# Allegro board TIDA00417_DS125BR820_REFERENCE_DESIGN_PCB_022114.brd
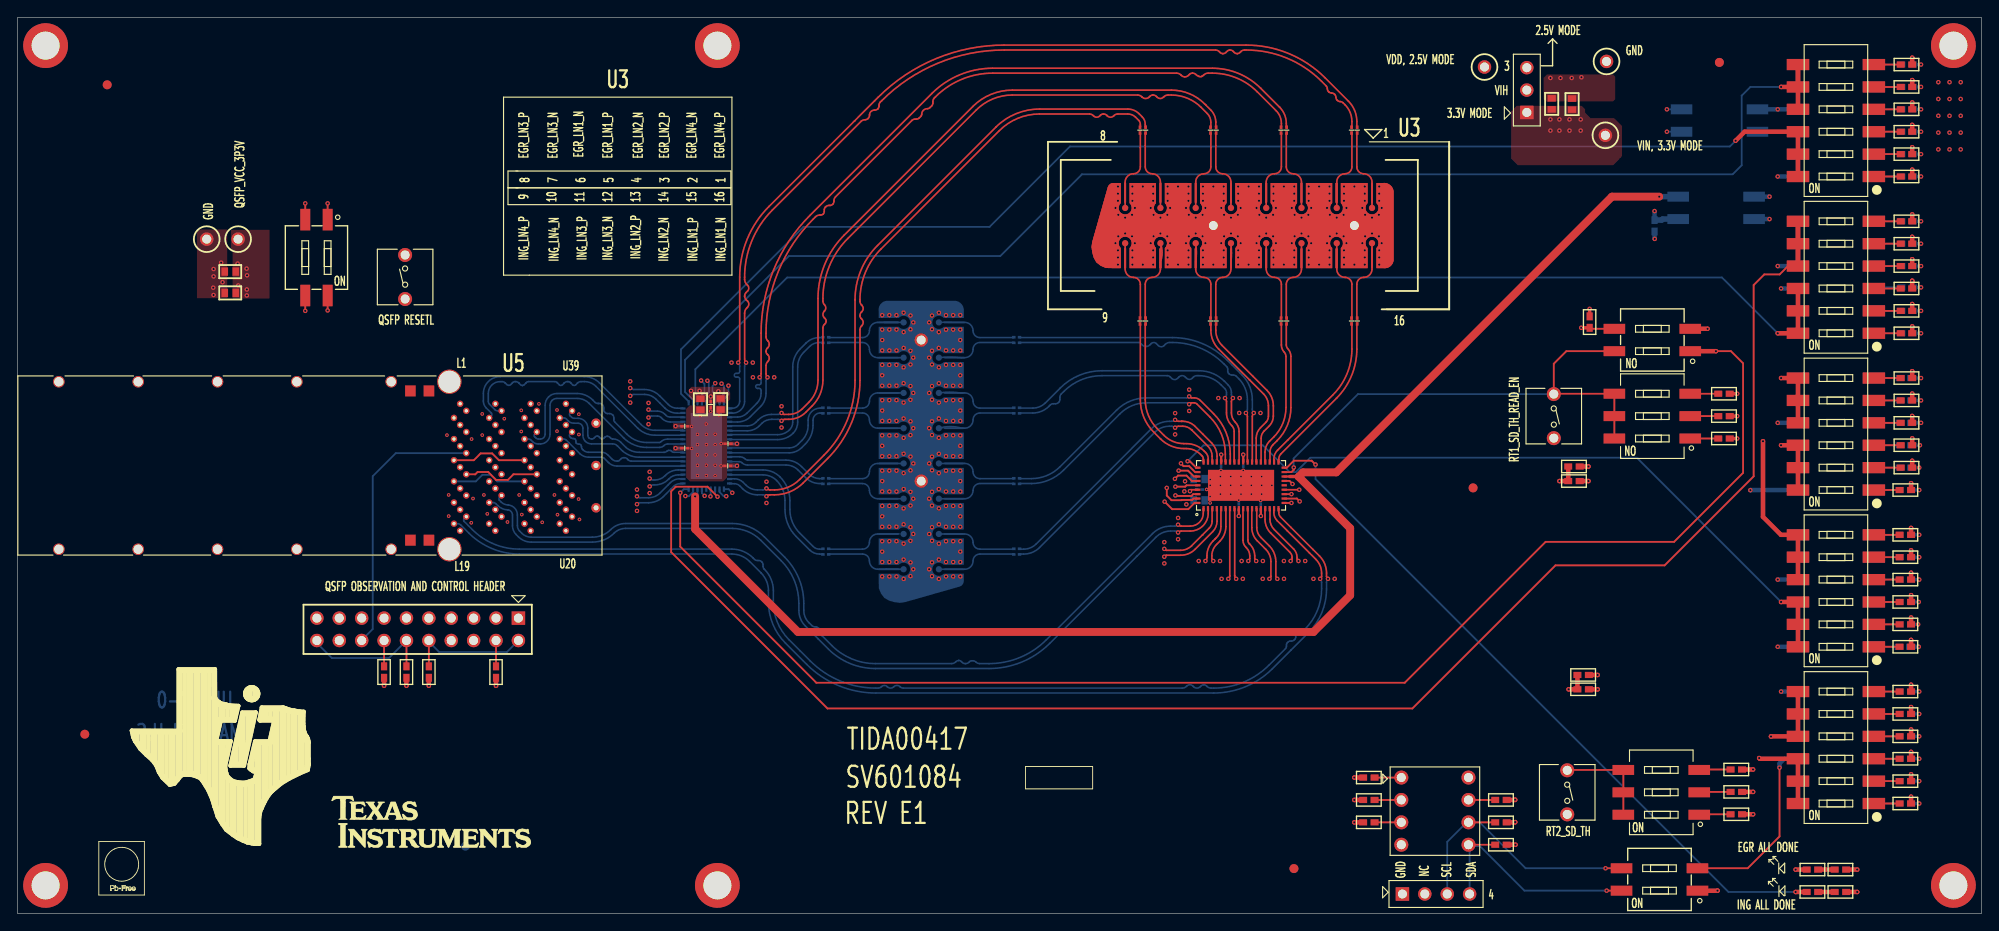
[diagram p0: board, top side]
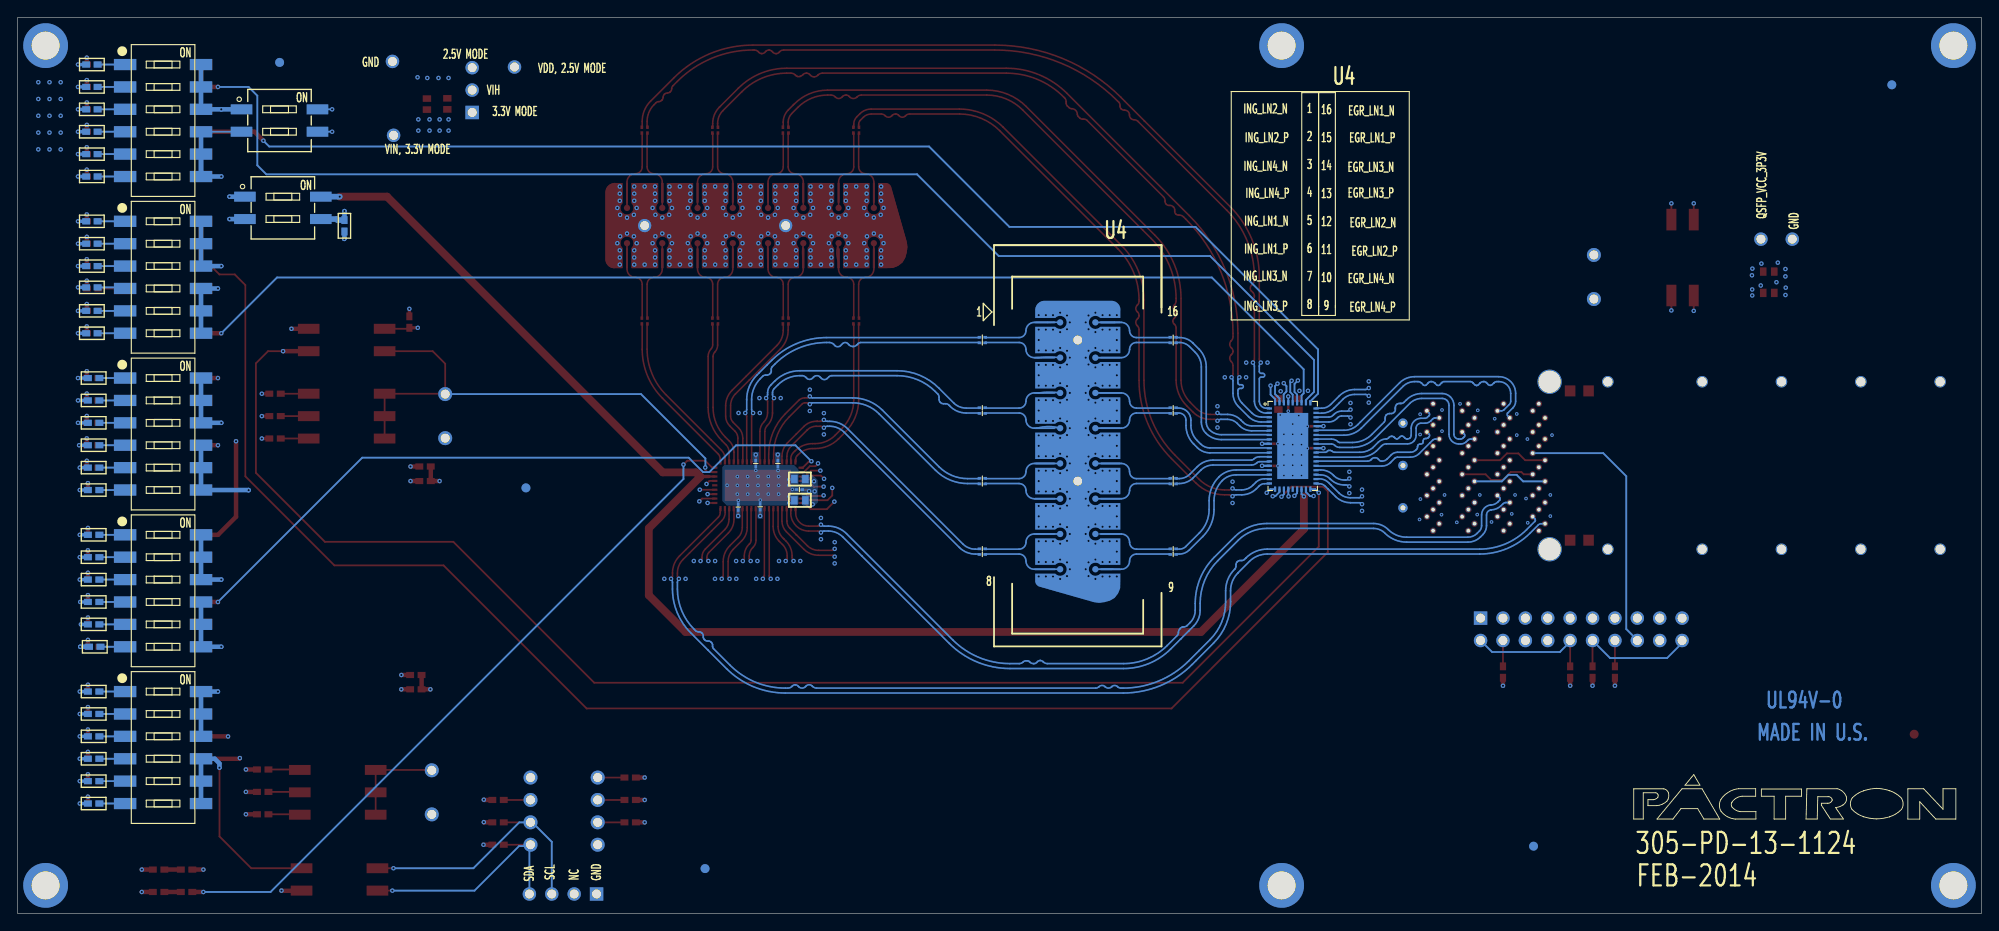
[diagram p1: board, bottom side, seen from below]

Outline 222.76 x 101.6 mm; copper layers: TOP, GND-1, SIG-1, PWR-1, GND-2, SIG-2, GND-3, SIG-3, GND-4, BOTTOM. Coordinates in mm from the lower left corner of the outline.
Outline path: 0,101.6 0,0 222.76,0 222.76,101.6 0,101.6

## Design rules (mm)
net group DIFFPAIR0: nets BOT_EGR_LN2_N BOT_EGR_LN2_P
net group DIFFPAIR1: nets BOT_EGR_LN4_N BOT_EGR_LN4_P
net group DIFFPAIR2: nets BOT_ING_LN1_N BOT_ING_LN1_P
net group DIFFPAIR3: nets BOT_ING_LN3_N BOT_ING_LN3_P
net group DIFFPAIR4: nets TOP_EGR_LN2_N TOP_EGR_LN2_P
net group DIFFPAIR5: nets TOP_EGR_LN4_N TOP_EGR_LN4_P
net group DIFFPAIR6: nets TOP_ING_LN1_N TOP_ING_LN1_P
net group DIFFPAIR8: nets BOT_EGR_LN3_N BOT_EGR_LN3_P
net group DIFFPAIR9: nets BOT_EGR_LN1_N BOT_EGR_LN1_P
net group DIFFPAIR11: nets BOT_ING_LN2_N BOT_ING_LN2_P
net group DIFFPAIR12: nets TOP_EGR_LN3_N TOP_EGR_LN3_P
net group DIFFPAIR13: nets TOP_EGR_LN1_N TOP_EGR_LN1_P
net group DIFFPAIR14: nets TOP_ING_LN4_N TOP_ING_LN4_P
net group DIFFPAIR15: nets TOP_ING_LN2_N TOP_ING_LN2_P
net group DIFFPAIR16: nets N16748108 N16748114
net group DIFFPAIR17: nets N16748184 N16748188
net group DIFFPAIR18: nets N16748192 N16748196
net group DIFFPAIR19: nets N16748388 N16748392
net group DIFFPAIR20: nets N16748072 N16748078
net group DIFFPAIR21: nets N16748084 N16748090
net group DIFFPAIR22: nets N16748096 N16748102
net group DIFFPAIR23: nets N16748396 N16748400
net group DIFFPAIR24: nets TOP_ING_LN3_HOST_N TOP_ING_LN3_HOST_P
net group DIFFPAIR25: nets TOP_ING_LN1_HOST_N TOP_ING_LN1_HOST_P
net group DIFFPAIR26: nets TOP_ING_LN4_HOST_N TOP_ING_LN4_HOST_P
net group DIFFPAIR27: nets TOP_ING_LN2_HOST_N TOP_ING_LN2_HOST_P
net group DIFFPAIR30: nets N16781834 N16781836
net group DIFFPAIR31: nets N16756955 N16756959
net group DIFFPAIR32: nets N16756979 N16756983
net group DIFFPAIR33: nets N16757079 N16757083
net group DIFFPAIR34: nets N16757087 N16757091
net group DIFFPAIR35: nets BOT_EGR_LN3_HOST_N BOT_EGR_LN3_HOST_P
net group DIFFPAIR36: nets BOT_EGR_LN1_HOST_N BOT_EGR_LN1_HOST_P
net group DIFFPAIR37: nets BOT_EGR_LN2_HOST_N BOT_EGR_LN2_HOST_P
net group DIFFPAIR38: nets BOT_EGR_LN4_HOST_N BOT_EGR_LN4_HOST_P
net group DIFFPAIR39: nets BOT_ING_LN1_HOST_N BOT_ING_LN1_HOST_P
net group DIFFPAIR40: nets BOT_ING_LN2_HOST_N BOT_ING_LN2_HOST_P
net group DIFFPAIR41: nets BOT_ING_LN3_HOST_N BOT_ING_LN3_HOST_P
net group DIFFPAIR42: nets BOT_ING_LN4_HOST_N BOT_ING_LN4_HOST_P
net group DIFFPAIR43: nets N16756859 N16756863
net group DIFFPAIR44: nets TOP_EGR_LN1_HOST_N TOP_EGR_LN1_HOST_P
net group DIFFPAIR45: nets TOP_EGR_LN3_HOST_N TOP_EGR_LN3_HOST_P
net group DIFFPAIR46: nets TOP_EGR_LN2_HOST_N TOP_EGR_LN2_HOST_P
net group DIFFPAIR47: nets TOP_EGR_LN4_HOST_N TOP_EGR_LN4_HOST_P

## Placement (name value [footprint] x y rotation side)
C1  0.1 uF  [C_0201]  151.95 88.84 90 top
C2  0.1 uF  [C_0201]  151.32 88.84 90 top
C3  0.1 uF  [C_0201]  143.95 88.84 90 top
C4  0.1 uF  [C_0201]  143.32 88.84 90 top
C5  0.1 uF  [C_0201]  135.95 88.84 90 top
C6  0.1 uF  [C_0201]  135.32 88.84 90 top
C7  0.1 uF  [C_0201]  91.68 65.35 180 bottom
C8  0.1 uF  [C_0201]  91.68 64.71 180 bottom
C9  0.1 uF  [C_0201]  91.68 57.35 180 bottom
C10  0.1 uF  [C_0201]  91.68 56.71 180 bottom
C11  0.1 uF  [C_0201]  91.68 49.35 180 bottom
C12  0.1 uF  [C_0201]  91.68 48.71 180 bottom
C13  0.1 uF  [C_0201]  91.68 41.35 180 bottom
C14  0.1 uF  [C_0201]  91.68 40.71 180 bottom
C15  0.1 uF  [C_0201]  127.95 88.84 90 top
C16  0.1 uF  [C_0201]  127.32 88.84 90 top
C17  0.1uF  [0201]  75.68 55.25 180 top
C18  0.1uF  [0201]  75.68 52.76 180 top
C19  0.1uF  [0201]  80.56 50.76 0 top
C20  0.1uF  [0201]  80.58 53.27 0 top
C21  0.1uF  [0201]  78.63 57.72 90 top
C22  10uF  [0603]  176.33 91.79 270 top
C23  1uF  [0603]  174.02 91.82 270 top
C24  0.1 uF  [C_0201]  127.32 67.19 270 top
C25  0.1 uF  [C_0201]  127.95 67.19 270 top
C26  0.1 uF  [C_0201]  113.33 40.71 0 bottom
C27  0.1 uF  [C_0201]  113.33 41.35 0 bottom
C28  0.1 uF  [C_0201]  113.33 48.71 0 bottom
C29  0.1 uF  [C_0201]  113.33 49.35 0 bottom
C30  0.1 uF  [C_0201]  113.33 56.71 0 bottom
C31  0.1 uF  [C_0201]  113.33 57.35 0 bottom
C32  0.1 uF  [C_0201]  113.33 64.71 0 bottom
C33  0.1 uF  [C_0201]  113.33 65.35 0 bottom
C34  0.1 uF  [C_0201]  135.32 67.19 270 top
C35  0.1 uF  [C_0201]  135.95 67.19 270 top
C36  0.1 uF  [C_0201]  143.32 67.19 270 top
C37  0.1 uF  [C_0201]  143.95 67.19 270 top
C38  0.1 uF  [C_0201]  151.32 67.19 270 top
C39  0.1 uF  [C_0201]  151.95 67.19 270 top
C40  0.1uF  [0201]  138.52 46.11 270 bottom
C41  0.1uF  [0201]  141.01 46.09 270 bottom
C42  0.1uF  [0201]  134.08 48.07 180 bottom
C43  0.1uF  [0201]  136.52 51.01 90 bottom
C44  0.1uF  [0201]  139.03 51.01 90 bottom
C45  1uF  [0603]  24.12 70.38 0 top
C46  10uF  [0603]  24.12 72.79 0 top
C47  1uF  [0603]  77.46 57.75 90 top
C48  10uF  [0603]  79.74 57.77 90 top
C49  1uF  [0603]  134.02 46.85 180 bottom
C50  10uF  [0603]  134.02 49.26 180 bottom
D1  SML-P12PTT86  [D0402]  203.59 4.97 0 top
D2  SML-P12PTT86  [D0402]  203.59 2.43 0 top
J1  4 HEADER  [4_HEADER]  160.9 2.2 0 top
J2  4808-3004-CP  [DIP8]  160.77 11.6 270 top
J3  HEADER 3  [3_HEADER]  171.2 93.38 90 top
J4  HEADER 10x2/SM  [HEADER_10X2_SM]  56.81 33.49 180 top
NOREF  -  [unnamed]  219.58 3.17 0 top
NOREF#2  -  [unnamed]  10.16 93.98 0 top
NOREF#3  -  [unnamed]  219.58 98.42 0 top
NOREF#4  -  [unnamed]  79.38 3.17 0 top
NOREF#5  -  [unnamed]  3.17 98.42 0 top
NOREF#6  -  [#2]  3.17 3.17 0 top
NOREF#7  -  [#2]  127 50.8 0 top
NOREF#8  -  [#2]  410.92 138.18 0 top
NOREF#9  -  [unnamed]  3.17 3.17 0 top
NOREF#10  -  [#2]  0 0 0 top
NOREF#11  -  [#2]  3.17 98.42 0 top
NOREF#12  -  [#2]  219.58 3.17 0 top
NOREF#13  -  [#2]  219.58 98.42 0 top
NOREF#14  -  [unnamed]  79.38 98.42 0 top
NOREF#15  -  [#2]  219.58 98.42 0 top
NOREF#16  -  [#2]  79.38 3.17 0 top
NOREF#17  -  [#2]  162.31 -84.07 0 top
NOREF#18  -  [unnamed]  165.1 48.26 0 top
NOREF#19  -  [#2]  3.17 3.17 0 top
NOREF#20  -  [#2]  3.17 98.42 0 top
NOREF#21  -  [unnamed]  144.78 5.08 0 top
NOREF#22  -  [#2]  219.58 3.17 0 top
NOREF#23  -  [#2]  79.38 98.42 0 top
NOREF#24  -  [unnamed]  193.04 96.52 0 top
NOREF#25  -  [unnamed]  7.62 20.32 0 top
NOREF#26  -  [#2]  210.92 239.22 0 top
NOREF#27  -  [#2]  213.77 213.05 0 top
NOREF#28  -  [#2]  0 0 0 top
NOREF#29  -  [unnamed]  193.04 96.52 180 bottom
NOREF#30  -  [unnamed]  50.8 7.62 180 bottom
NOREF#31  -  [#2]  465.86 162.71 180 bottom
NOREF#32  -  [unnamed]  165.1 48.26 180 bottom
NOREF#33  -  [unnamed]  144.78 5.08 180 bottom
NOREF#34  -  [#2]  469.04 165.89 180 bottom
NOREF#35  -  [unnamed]  10.16 93.98 180 bottom
NOREF#36  -  [#2]  446.18 174.96 180 bottom
NOREF#37  -  [#2]  469.04 165.89 90 bottom
NOREF#38  -  [#2]  472.24 177.04 180 bottom
R1  1k  [0402]  214.26 83.58 180 top
R2  1k  [0402]  168.26 12.87 0 top
R3  20k  [0402]  214.26 86.12 180 top
R4  1k  [0402]  153.28 15.41 0 top
R5  4.7k_DNL  [0402]  168.26 10.33 0 top
R6  4.7k  [0402]  168.26 7.79 0 top
R7  1k  [0402]  214.26 88.66 180 top
R8  1k  [0402]  214.26 91.2 180 top
R9  1k  [0402]  153.28 12.87 0 top
R10  20k  [0402]  214.26 93.74 180 top
R11  1k  [0402]  153.28 10.33 0 top
R12  1k  [0402]  214.26 96.28 180 top
R13  1k  [0402]  214.34 96.28 180 bottom
R14  1k  [0402]  214.34 78.5 180 bottom
R15  1k  [0402]  214.34 73.42 180 bottom
R16  20k  [0402]  214.34 93.74 180 bottom
R17  20k  [0402]  214.34 75.96 180 bottom
R18  1k  [0402]  214.34 91.2 180 bottom
R19  1k  [0402]  214.34 88.66 180 bottom
R20  1k  [0402]  214.34 71.01 180 bottom
R21  20k  [0402]  214.34 86.12 180 bottom
R22  20k  [0402]  214.34 68.34 180 bottom
R23  1k  [0402]  214.34 83.58 180 bottom
R24  1k  [0402]  214.34 65.8 180 bottom
R25  1k  [0402]  214.13 12.46 180 top
R26  1k  [0402]  194.96 11.24 180 top
R27  20k  [0402]  214.13 15 180 top
R28  20k  [0402]  194.96 13.78 180 top
R29  1k  [0402]  214.13 17.54 180 top
R30  1k  [0402]  194.96 16.32 180 top
R31  1k  [0402]  214.13 20.08 180 top
R32  20k  [0402]  214.13 22.62 180 top
R33  1k  [0402]  214.13 25.16 180 top
R34  220  [0402]  206.77 4.97 0 top
R35  1k  [0402]  214.26 65.8 180 top
R36  20k  [0402]  214.26 68.34 180 top
R37  1k  [0402]  214.26 70.88 180 top
R38  1k  [0402]  214.26 73.42 180 top
R39  20k  [0402]  214.26 75.96 180 top
R40  1k  [0402]  214.26 78.5 180 top
R41  1k  [0402]  177.58 25.41 0 top
R42  1k  [0402]  185.69 77.99 90 bottom
R43  BOM=NO  [0402]  177.58 27.04 180 top
R44  1k  [0402]  214.13 30.24 180 top
R45  1k  [0402]  214.13 35.32 180 top
R46  20k  [0402]  214.13 32.78 180 top
R47  1k  [0402]  214.13 37.86 180 top
R48  20k  [0402]  214.13 40.4 180 top
R49  1k  [0402]  214.13 42.94 180 top
R50  1k  [0402]  214.13 25.16 180 bottom
R51  20k  [0402]  214.13 22.62 180 bottom
R52  1k  [0402]  214.13 48.02 180 top
R53  20k  [0402]  214.26 50.56 180 top
R54  1k  [0402]  214.13 20.08 180 bottom
R55  1k  [0402]  214.26 53.1 180 top
R56  1k  [0402]  214.13 17.54 180 bottom
R57  1k  [0402]  214.26 55.64 180 top
R58  20k  [0402]  214.13 15 180 bottom
R59  20k  [0402]  214.26 58.18 180 top
R60  1k  [0402]  214.13 12.46 180 bottom
R61  1k  [0402]  214.26 60.72 180 top
R62  1k  [0402]  214.13 42.94 180 bottom
R63  1k  [0402]  193.56 53.86 180 top
R64  20k  [0402]  193.56 56.4 180 top
R65  1k  [0402]  193.56 58.94 180 top
R66  20k  [0402]  214.13 40.4 180 bottom
R67  1k  [0402]  214.13 37.86 180 bottom
R68  1k  [0402]  214.13 35.32 180 bottom
R69  20k  [0402]  214.13 32.78 180 bottom
R70  1k  [0402]  214.01 30.24 180 bottom
R71  220  [0402]  206.77 2.43 0 top
R72  1k  [0402]  214.13 60.72 180 bottom
R73  20k  [0402]  214.13 58.18 180 bottom
R74  1k  [0402]  178.32 67.07 270 top
R75  1k  [0402]  214.13 55.64 180 bottom
R76  1k  [0402]  214.13 53.1 180 bottom
R77  20k  [0402]  214.13 50.56 180 bottom
R78  1k  [0402]  214.13 48.02 180 bottom
R79  1k  [0402]  176.54 49.03 0 top
R80  BOM=NO  [0402]  176.54 50.69 180 top
R81  4.7K  [R_0402]  41.57 27.37 270 top
R82  4.7K  [R_0402]  44.11 27.37 270 top
R83  4.7K  [R_0402]  54.27 27.37 270 top
R84  4.7K  [R_0402]  46.65 27.37 270 top
SW1  219-6MST  [219_6MST]  206.26 89.93 180 top
SW2  219-2MST  [219_2MST]  193.05 89.93 180 bottom
SW3  219-6MST  [219_6MST]  206.26 72.15 180 bottom
SW4  219-6MST  [219_6MST]  206.26 89.93 180 bottom
SW5  219-6MST  [219_6MST]  206.26 18.81 180 top
SW6  219-3MST  [219_3MST]  186.45 13.73 180 top
SW7  EVQ-21505R  [EVQ_21505R]  175.78 13.73 270 top
SW8  219-6MST  [219_6MST]  206.26 72.15 180 top
SW9  219-2MST  [219_2MST]  192.67 80.02 180 bottom
SW10  219-6MST  [219_6MST]  206.26 36.59 180 top
SW11  219-6MST  [219_6MST]  206.26 18.81 180 bottom
SW12  219-6MST  [219_6MST]  206.26 54.37 180 top
SW13  219-2MST  [219_2MST]  186.25 3.85 180 top
SW14  219-6MST  [219_6MST]  206.26 36.59 180 bottom
SW15  219-3MST  [219_3MST]  185.43 56.4 180 top
SW16  EVQ-21505R  [EVQ_21505R]  174.26 56.4 270 top
SW17  219-2MST  [219_2MST]  185.43 65.04 180 top
SW18  219-6MST  [219_6MST]  206.26 54.37 180 bottom
SW19  219-2MST  [219_2MST]  33.9 74.38 270 top
SW20  -  [SW_PB_SPST]  43.95 72.18 90 top
TP1  TEST POINT  [0_100X0_100INCH]  180.11 88.25 180 top
TP2  TEST POINT  [0_100X0_100INCH]  180.24 96.63 180 top
TP3  TEST POINT  [0_100X0_100INCH]  166.4 96 180 top
TP4  TEST POINT  [0_100X0_100INCH]  25.01 76.47 270 top
TP5  TEST POINT  [0_100X0_100INCH]  21.45 76.47 270 top
U1  DS100KR800  [54_LLP]  138.78 48.55 90 top
U2  DS100KR800  [54_LLP]  78.12 53.02 180 bottom
U3  2x8A_81_MXP-S50-0-1  [2X8A_81_MXP_S50_0_1]  139.63 78.02 0 top
U4  2x8A_81_MXP-S50-0-1  [2X8A_81_MXP_S50_0_1_U4]  102.5 53.03 90 bottom
U5  Molex_zQSFP_cage  [MOLEX_ZQSFP_CAGE]  33.16 50.8 0 top

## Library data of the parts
C1-C16 C24-C39 = CAP NP
C17-C23 C40-C50 = C
D1 D2 = 1091QM_0
J1 = 4 HEADER
J2 = DIP8 SOCKET
J3 = HEADER 3
J4 = HEADER 10x2/SM
R1 R3 R4 R7-R80 = RESISTOR
R2 R5 R6 = RESISTOR/SM
R81-R84 = R
SW1 SW3-SW5 SW8 SW10-SW12 SW14 SW18 = SW DIP-6/SM
SW2 SW9 SW13 SW17 SW19 = SW DIP-2/SM
SW6 SW15 = SW DIP-3/SM
SW7 SW16 = SW PUSHBUTTON-SPST
SW20 = SW_PUSHBUTTON_SPST
TP1-TP5 = TEST POINT
U1 U2 = DS100KR800
U3 U4 = 2x8A_81_MXP-S50-0-1_0
U5 = Molex_zQSFP_cage_0

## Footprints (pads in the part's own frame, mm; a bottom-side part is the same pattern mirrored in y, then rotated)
0_100X0_100INCH
  round 1.524 hole 1.016: 1(0,0)
2X8A_81_MXP_S50_0_1
  round 0.714 smd: 1(14,2) 2(10,2) 3(6,2) 4(2,2) 5(-2,2) 6(-6,2) 7(-10,2) 8(-14,2) 9(-14,-2) 10(-10,-2) 11(-6,-2) 12(-2,-2) 13(2,-2) 14(6,-2) 15(10,-2) 16(14,-2)
  round 1.5 hole 1: 17(-4,0) 18(12,0)
2X8A_81_MXP_S50_0_1_U4
  round 0.714 smd: 1(14,2) 2(10,2) 3(6,2) 4(2,2) 5(-2,2) 6(-6,2) 7(-10,2) 8(-14,2) 9(-14,-2) 10(-10,-2) 11(-6,-2) 12(-2,-2) 13(2,-2) 14(6,-2) 15(10,-2) 16(14,-2)
  round 1.5 hole 1: 17(-4,0) 18(12,0)
3_HEADER
  rect 1.524x1.524 hole 1.016: 1(-2.54,0)
  round 1.524 hole 1.016: 2(0,0) 3(2.54,0)
4_HEADER
  rect 1.524x1.524 hole 1.016: 1(-3.81,0)
  round 1.524 hole 1.016: 2(-1.27,0) 3(1.27,0) 4(3.81,0)
54_LLP
  rect 0.6x0.25 smd: 1(-2.65,4.25) 2(-2.65,3.75) 3(-2.65,3.25) 4(-2.65,2.75) 5(-2.65,2.25) 6(-2.65,1.75) 7(-2.65,1.25) 8(-2.65,0.75) 9(-2.65,0.25) 10(-2.65,-0.25) 11(-2.65,-0.75) 12(-2.65,-1.25) 13(-2.65,-1.75) 14(-2.65,-2.25) 15(-2.65,-2.75) 16(-2.65,-3.25) 17(-2.65,-3.75) 18(-2.65,-4.25) 28(2.65,-4.25) 29(2.65,-3.75) 30(2.65,-3.25) 31(2.65,-2.75) 32(2.65,-2.25) 33(2.65,-1.75) 34(2.65,-1.25) 35(2.65,-0.75) 36(2.65,-0.25) 37(2.65,0.25) 38(2.65,0.75) 39(2.65,1.25) 40(2.65,1.75) 41(2.65,2.25) 42(2.65,2.75) 43(2.65,3.25) 44(2.65,3.75) 45(2.65,4.25)
  rect 0.25x0.6 smd: 19(-2,-4.9) 20(-1.5,-4.9) 21(-1,-4.9) 22(-0.5,-4.9) 23(0,-4.9) 24(0.5,-4.9) 25(1,-4.9) 26(1.5,-4.9) 27(2,-4.9) 46(2,4.9) 47(1.5,4.9) 48(1,4.9) 49(0.5,4.9) 50(0,4.9) 51(-0.5,4.9) 52(-1,4.9) 53(-1.5,4.9) 54(-2,4.9)
  rect 3.51x7.5 smd: 55(0,0)
0201
  rect 0.4x0.3 smd: 1(-0.33,0) 2(0.33,0)
219_2MST
  rect 2.45x1.13 smd: 1(-4.305,1.27) 2(-4.305,-1.27) 3(4.305,-1.27) 4(4.305,1.27)
219_3MST
  rect 2.45x1.13 smd: 1(-4.305,2.54) 2(-4.305,0) 3(-4.305,-2.54) 4(4.305,-2.54) 5(4.305,0) 6(4.305,2.54)
219_6MST
  rect 2.54x1.27 smd: 1(-4.305,6.35) 2(-4.305,3.81) 3(-4.305,1.27) 4(-4.305,-1.27) 5(-4.305,-3.81) 6(-4.305,-6.35) 7(4.305,-6.35) 8(4.305,-3.81) 9(4.305,-1.27) 10(4.305,1.27) 11(4.305,3.81) 12(4.305,6.35)
0402
  rect 0.9x0.7 smd: 1(-0.65,0) 2(0.65,0)
0603
  rect 0.749x0.95 smd: 1(-0.625,0) 2(0.625,0)
C_0201
  rect 0.4x0.3 smd: 1(-0.33,0) 2(0.33,0)
D0402
  rect 0.9x0.7 smd: 1(-0.65,0) 2(0.65,0)
DIP8
  round 1.584 hole 1.016: 1(-3.81,-3.81) 2(-1.27,-3.81) 3(1.27,-3.81) 4(3.81,-3.81) 5(3.81,3.81) 6(1.27,3.81) 7(-1.27,3.81) 8(-3.81,3.81)
EVQ_21505R
  round 1.584 hole 1.016: 1(-2.5,0) 2(2.5,0)
HEADER_10X2_SM
  rect 1.524x1.524 hole 1.016: 1(0,0)
  round 1.524 hole 1.016: 2(0,2.54) 3(2.54,0) 4(2.54,2.54) 5(5.08,0) 6(5.08,2.54) 7(7.62,0) 8(7.62,2.54) 9(10.16,0) 10(10.16,2.54) 11(12.7,0) 12(12.7,2.54) 13(15.24,0) 14(15.24,2.54) 15(17.78,0) 16(17.78,2.54) 17(20.32,0) 18(20.32,2.54) 19(22.86,0) 20(22.86,2.54)
MOLEX_ZQSFP_CAGE
  rect 1.2x1.25 smd: (11.4,8.46) (11.4,-8.47) (13.5,8.46) (13.5,-8.47)
  round 2.754 hole 2.5: (15.82,9.5) (15.82,-9.5)
  round 1.304 hole 1.05: C1(-28.48,9.5) C2(-19.48,9.5) C3(-10.48,9.5) C4(-1.48,9.5) C5(9.22,9.5) C9(9.22,-9.5) C10(-1.48,-9.5) C11(-10.48,-9.5) C12(-19.48,-9.5) C13(-28.48,-9.5)
  round 1.068 hole 0.56: C6(32.46,4.8) C7(32.46,0) C8(32.46,-4.8)
  round 0.73 hole 0.37: L1(17.04,7) L2(17.74,6.2) L3(16.34,5.4) L4(17.04,4.6) L5(17.74,3.8) L6(16.34,3) L7(17.04,2.2) L8(17.74,1.4) L9(16.34,0.6) L10(17.04,-0.2) L11(17.74,-1) L12(16.34,-1.8) L13(17.04,-2.6) L14(17.74,-3.4) L15(16.34,-4.2) L16(17.04,-5) L17(17.74,-5.8) L18(16.34,-6.6) L19(17.04,-7.4) L20(21.04,-7.4) L21(20.34,-6.6) L22(21.74,-5.8) L23(21.04,-5) L24(20.34,-4.2) L25(21.74,-3.4) L26(21.04,-2.6) L27(20.34,-1.8) L28(21.74,-1) L29(21.04,-0.2) L30(20.34,0.6) L31(21.74,1.4) L32(21.04,2.2) L33(20.34,3) L34(21.74,3.8) L35(21.04,4.6) L36(20.34,5.4) L37(21.74,6.2) L38(21.04,7) U1(25.04,7) U2(25.74,6.2) U3(24.34,5.4) U4(25.04,4.6) U5(25.74,3.8) U6(24.34,3) U7(25.04,2.2) U8(25.74,1.4) U9(24.34,0.6) U10(25.04,-0.2) U11(25.74,-1) U12(24.34,-1.8) U13(25.04,-2.6) U14(25.74,-3.4) U15(24.34,-4.2) U16(25.04,-5) U17(25.74,-5.8) U18(24.34,-6.6) U19(25.04,-7.4) U20(29.04,-7.4) U21(28.34,-6.6) U22(29.74,-5.8) U23(29.04,-5) U24(28.34,-4.2) U25(29.74,-3.4) U26(29.04,-2.6) U27(28.34,-1.8) U28(29.74,-1) U29(29.04,-0.2) U30(28.34,0.6) U31(29.74,1.4) U32(29.04,2.2) U33(28.34,3) U34(29.74,3.8) U35(29.04,4.6) U36(28.34,5.4) U37(29.74,6.2) U38(29.04,7)
R_0402
  rect 0.9x0.7 smd: 1(-0.65,0) 2(0.65,0)
SW_PB_SPST
  round 1.584 hole 1.016: 1(-2.5,0) 2(2.5,0)
unnamed
  round 5.08 hole 3.175 unplated: (0,0)

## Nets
GND: C17.1 C18.1 C19.1 C20.1 C21.1 C22.1 C23.1 C40.1 C41.1 C42.1 C43.1 C44.1 C45.1 C46.1 C47.1 C48.1 C49.1 C50.1 J1.1 J2.4 J4.1 J4.3 J4.5 J4.7 J4.9 J4.11 J4.13 J4.15 J4.17 J4.19 R3.1 R4.1 R7.1 R9.1 R10.1 R11.1 R12.1 R15.1 R16.1 R17.1 R18.1 R21.1 R22.1 R23.1 R24.1 R27.1 R28.1 R29.1 R30.1 R32.1 R33.1 R36.1 R37.1 R39.1 R40.1 R43.1 R45.1 R46.1 R48.1 R49.1 R51.1 R53.1 R54.1 R55.1 R58.1 R59.1 R60.1 R61.1 R64.1 R65.1 R66.1 R67.1 R69.1 R70.1 R73.1 R75.1 R77.1 R78.1 R80.1 SW7.2 SW9.1(A1) SW9.2(A2) SW16.2 SW17.2(A2) SW20.2 TP2.1 TP5.1 U1.55(DAP) U2.55(DAP) U3.17(GND#17) U3.18(GND#18) U4.17(GND#17) U4.18(GND#18) U5.C1(GND25) U5.C2(GND26) U5.C3(GND27) U5.C4(GND28) U5.C5(GND29) U5.C6(GND30) U5.C7(GND31) U5.C8(GND32) U5.C9(GND33) U5.C10(GND34) U5.C11(GND35) U5.C12(GND36) U5.C13(GND37) U5.L1(GND13) U5.L4(GND14) U5.L7(GND15) U5.L13(GND16) U5.L16(GND17) U5.L19(GND18) U5.L20(GND19) U5.L23(GND20) U5.L26(GND21) U5.L32(GND22) U5.L35(GND23) U5.L38(GND24) U5.U1(GND1) U5.U4(GND2) U5.U7(GND3) U5.U13(GND4) U5.U16(GND5) U5.U19(GND6) U5.U20(GND7) U5.U23(GND8) U5.U26(GND9) U5.U32(GND10) U5.U35(GND11) U5.U38(GND12)
VDD: C17.2 C18.2 C19.2 C20.2 C21.2 C40.2 C41.2 C42.2 C43.2 C44.2 C47.2 C48.2 C49.2 C50.2 J3.3 TP3.1 U1.9(VDD#9) U1.14(VDD#14) U1.36(VDD#36) U1.41(VDD#41) U1.51(VDD#51) U2.9(VDD#9) U2.14(VDD#14) U2.36(VDD#36) U2.41(VDD#41) U2.51(VDD#51)
VDD_SEL: SW9.4(B1) U1.25(VDD_SEL) U2.25(VDD_SEL)
VIN: C22.2 C23.2 J3.1 TP1.1 U1.24(VIN) U2.24(VIN)
BOT_EGR_LN1_HOST_N: C6.1 U3.6(PIN6)
BOT_EGR_LN1_HOST_P: C5.1 U3.5(PIN5)
BOT_EGR_LN1_N: U2.39(OB_2-) U5.L37(BOT_TX1N)
BOT_EGR_LN1_P: U2.40(OB_2+) U5.L36(BOT_TX1P)
BOT_EGR_LN2_HOST_N: C4.1 U3.4(PIN4)
BOT_EGR_LN2_HOST_P: C3.1 U3.3(PIN3)
BOT_EGR_LN2_N: U2.42(OB_1-) U5.L2(BOT_TX2N)
BOT_EGR_LN2_P: U2.43(OB_1+) U5.L3(BOT_TX2P)
BOT_EGR_LN3_HOST_N: C15.1 U3.7(PIN7)
BOT_EGR_LN3_HOST_P: C16.1 U3.8(PIN8)
BOT_EGR_LN3_N: U2.29(OA_3+) U5.L34(BOT_TX3N)
BOT_EGR_LN3_P: U2.28(OA_3-) U5.L33(BOT_TX3P)
BOT_EGR_LN4_HOST_N: C2.1 U3.2(PIN2)
BOT_EGR_LN4_HOST_P: C1.1 U3.1(PIN1)
BOT_EGR_LN4_N: U2.44(OB_0-) U5.L5(BOT_TX4N)
BOT_EGR_LN4_P: U2.45(OB_0+) U5.L6(BOT_TX4P)
BOT_ING_LN1_HOST_N: C39.1 U3.16(PIN16)
BOT_ING_LN1_HOST_P: C38.1 U3.15(PIN15)
BOT_ING_LN1_N: U1.18(IA_3-) U5.L18(BOTRX1N)
BOT_ING_LN1_P: U1.17(IA_3+) U5.L17(BOT_RX1P)
BOT_ING_LN2_HOST_N: C37.1 U3.14(PIN14)
BOT_ING_LN2_HOST_P: C36.1 U3.13(PIN13)
BOT_ING_LN2_N: U1.16(IA_2-) U5.L15(BOT_RX3N)
BOT_ING_LN2_P: U1.15(IA_2+) U5.L14(BOT_RX3P)
BOT_ING_LN3_HOST_N: C35.1 U3.12(PIN12)
BOT_ING_LN3_HOST_P: C34.1 U3.11(PIN11)
BOT_ING_LN3_N: U1.13(IA_1-) U5.L21(BOT_RX2N)
BOT_ING_LN3_P: U1.12(IA_1+) U5.L22(BOT_RX2P)
BOT_ING_LN4_HOST_N: C25.1 U3.10(PIN10)
BOT_ING_LN4_HOST_P: C24.1 U3.9(PIN9)
BOT_ING_LN4_N: U1.2(IB_0-) U5.L24(BOT_RX4N)
BOT_ING_LN4_P: U1.1(IB_0+) U5.L25(BOT_RX4P)
BOT_INTL: J4.14 R81.1 U5.L28(BOT_INTL)
BOT_LPMODE: J4.18 U5.L31(BOT_LPMODE)
BOT_MODPRSL: J4.12 J4.20 R82.1 U5.L27(BOT_MODPRSL)
BOT_MODSELL: J4.16 U5.L8(BOT_MODSELL)
QSFP_RESETL: SW20.1 U5.L9(BOT_RESETL) U5.U9(TOP_RESETL)
QSFP_SCL: SW19.3(B2) U5.L11(BOT_SCL) U5.U11(TOP_SCL)
QSFP_SDA: SW19.4(B1) U5.L12(BOT_SDA) U5.U12(TOP_SDA)
QSFP_VCC_3P3V: C45.2 C46.2 R81.2 R82.2 R83.2 R84.2 TP4.1 U5.L10(BOT_VCC_RX) U5.L29(BOT_VCC_TX) U5.L30(BOT_VCC1) U5.U10(TOP_VCC_RX) U5.U29(TOP_VCC_TX) U5.U30(TOP_VCC1)
RT1_DEMA0_SDA: SW11.10(B3) SW11.11(B2) SW11.12(B1) SW13.1(A1) U1.49(DEMA0/SDA)
RT1_DEMA1_SCL: SW11.7(B6) SW11.8(B5) SW11.9(B4) SW13.2(A2) U1.50(DEMA1/SCL)
RT1_DEMB0_AD1: SW12.10(B3) SW12.11(B2) SW12.12(B1) U1.53(DEMB0/AD1)
RT1_DEMB1_AD0: SW12.7(B6) SW12.8(B5) SW12.9(B4) U1.54(DEMB1/AD0)
RT1_ENSMB: SW18.10(B3) SW18.11(B2) SW18.12(B1) U1.48(ENSMB)
RT1_EQA0: SW14.10(B3) SW14.11(B2) SW14.12(B1) U1.20(EQA0)
RT1_EQA1: SW14.7(B6) SW14.8(B5) SW14.9(B4) U1.19(EQA1)
RT1_EQB0_AD3: SW10.10(B3) SW10.11(B2) SW10.12(B1) U1.46(EQB0/AD3)
RT1_EQB1_AD2: SW10.7(B6) SW10.8(B5) SW10.9(B4) U1.47(EQB1/AD2)
RT1_INPUT_EN: R79.1 R80.2 U1.22(INPUT_EN)
RT1_MODE: SW18.7(B6) SW18.8(B5) SW18.9(B4) U1.21(MODE)
RT1_PWDN: R74.2 SW17.3(B2) U1.52(/RESET)
RT1_SD_TH_READ_EN: SW15.4(B3) SW15.5(B2) SW15.6(B1) SW16.1 SW17.4(B1) U1.26(SD_TH/RD_EN)
RT2_ALL_DONE: D1.1(CATHODE) SW17.1(A1) U2.27(ALL_DONE)
RT2_DEMA0_SDA: SW2.1(A1) SW4.10(B3) SW4.11(B2) SW4.12(B1) U2.49(DEMA0/SDA)
RT2_DEMA1_SCL: SW2.2(A2) SW4.7(B6) SW4.8(B5) SW4.9(B4) U2.50(DEMA1/SCL)
RT2_DEMB0_AD1: SW3.10(B3) SW3.11(B2) SW3.12(B1) U2.53(DEMB0/AD1)
RT2_DEMB1_AD0: SW3.7(B6) SW3.8(B5) SW3.9(B4) U2.54(DEMB1/AD0)
RT2_ENSMB: SW8.10(B3) SW8.11(B2) SW8.12(B1) U2.48(ENSMB)
RT2_EQA0: SW5.10(B3) SW5.11(B2) SW5.12(B1) U2.20(EQA0)
RT2_EQA1: SW5.7(B6) SW5.8(B5) SW5.9(B4) U2.19(EQA1)
RT2_EQB0_AD3: SW1.10(B3) SW1.11(B2) SW1.12(B1) U2.46(EQB0/AD3)
RT2_EQB1_AD2: SW1.7(B6) SW1.8(B5) SW1.9(B4) U2.47(EQB1/AD2)
RT2_INPUT_EN: R41.1 R43.2 U2.22(INPUT_EN)
RT2_MODE: SW8.7(B6) SW8.8(B5) SW8.9(B4) U2.21(MODE)
RT2_PWDN: R42.2 SW9.3(B2) U2.52(/RESET)
RT2_SD_TH: SW6.4(B3) SW6.5(B2) SW6.6(B1) SW7.1 U2.26(SD_TH/RD_EN)
SCL: J1.3 J2.6 R5.1 SW2.3(B2) SW13.3(B2) SW19.2(A2)
SDA: J1.4 J2.5 R6.1 SW2.4(B1) SW13.4(B1) SW19.1(A1)
TOP_EGR_LN1_HOST_N: C7.1 U4.16(PIN16)
TOP_EGR_LN1_HOST_P: C8.1 U4.15(PIN15)
TOP_EGR_LN1_N: U2.38(OB_3+) U5.U5(TOP_TX4N)
TOP_EGR_LN1_P: U2.37(OB_3-) U5.U6(TOP_TX4P)
TOP_EGR_LN2_HOST_N: C11.1 U4.12(PIN12)
TOP_EGR_LN2_HOST_P: C12.1 U4.11(PIN11)
TOP_EGR_LN2_N: U2.33(OA_1+) U5.U34(TOP_TX3N)
TOP_EGR_LN2_P: U2.32(OA_1-) U5.U33(TOP_TX3P)
TOP_EGR_LN3_HOST_N: C9.1 U4.14(PIN14)
TOP_EGR_LN3_HOST_P: C10.1 U4.13(PIN13)
TOP_EGR_LN3_N: U2.35(OA_0+) U5.U37(TOP_TX1N)
TOP_EGR_LN3_P: U2.34(OA_0-) U5.U36(TOP_TX1P)
TOP_EGR_LN4_HOST_N: C13.1 U4.10(PIN10)
TOP_EGR_LN4_HOST_P: C14.1 U4.9(PIN9)
TOP_EGR_LN4_N: U2.31(OA_2+) U5.U2(TOP_TX2N)
TOP_EGR_LN4_P: U2.30(OA_2-) U5.U3(TOP_TX2P)
TOP_ING_LN1_HOST_N: C29.1 U4.5(PIN5)
TOP_ING_LN1_HOST_P: C28.1 U4.6(PIN6)
TOP_ING_LN1_N: U1.6(IB_2-) U5.U21(TOP_RX2N)
TOP_ING_LN1_P: U1.5(IB_2+) U5.U22(TOP_RX2P)
TOP_ING_LN2_HOST_N: C33.1 U4.1(PIN1)
TOP_ING_LN2_HOST_P: C32.1 U4.2(PIN2)
TOP_ING_LN2_N: U1.11(IA_0-) U5.U15(TOP_RX3N)
TOP_ING_LN2_P: U1.10(IA_0+) U5.U14(TOP_RX3P)
TOP_ING_LN3_HOST_N: C27.1 U4.7(PIN7)
TOP_ING_LN3_HOST_P: C26.1 U4.8(PIN8)
TOP_ING_LN3_N: U1.4(IB_1-) U5.U24(TOP_RX4N)
TOP_ING_LN3_P: U1.3(IB_1+) U5.U25(TOP_RX4P)
TOP_ING_LN4_HOST_N: C31.1 U4.3(PIN3)
TOP_ING_LN4_HOST_P: C30.1 U4.4(PIN4)
TOP_ING_LN4_N: U1.8(IB_3-) U5.U18(TOP_RX1N)
TOP_ING_LN4_P: U1.7(IB_3+) U5.U17(TOP_RX1P)
TOP_INTL: J4.4 R83.1 U5.U28(TOP_INTL)
TOP_LPMODE: J4.8 U5.U31(TOP_LPMODE)
TOP_MODPRSL: J4.2 J4.10 R84.1 U5.U27(TOP_MODPRSL)
TOP_MODSELL: J4.6 U5.U8(TOP_MODSELL)
VIH: J2.8 J3.2 R1.1 R2.2 R5.2 R6.2 R8.1 R13.1 R14.1 R19.1 R20.1 R25.1 R26.1 R31.1 R34.2 R35.1 R38.1 R41.2 R42.1 R44.1 R47.1 R50.1 R52.1 R56.1 R57.1 R62.1 R63.1 R68.1 R71.2 R72.1 R74.1 R76.1 R79.2
N14524358: J2.3 R11.2
N14524360: J2.2 R9.2
N14524362: J2.1 R4.2
N14693554: J2.7 R2.1
N16748072: C1.2 U2.1(IB_0+)
N16748078: C2.2 U2.2(IB_0-)
N16748084: C3.2 U2.3(IB_1+)
N16748090: C4.2 U2.4(IB_1-)
N16748096: C5.2 U2.5(IB_2+)
N16748102: C6.2 U2.6(IB_2-)
N16748108: C7.2 U2.7(IB_3+)
N16748114: C8.2 U2.8(IB_3-)
N16748184: C10.2 U2.11(IA_0-)
N16748188: C9.2 U2.10(IA_0+)
N16748192: C12.2 U2.13(IA_1-)
N16748196: C11.2 U2.12(IA_1+)
N16748388: C13.2 U2.15(IA_2+)
N16748392: C14.2 U2.16(IA_2-)
N16748396: C15.2 U2.17(IA_3+)
N16748400: C16.2 U2.18(IA_3-)
N16756859: C24.2 U1.45(OB_0+)
N16756863: C25.2 U1.44(OB_0-)
N16756883: C26.2 U1.43(OB_1+)
N16756887: C27.2 U1.42(OB_1-)
N16756955: C33.2 U1.34(OA_0-)
N16756959: C32.2 U1.35(OA_0+)
N16756979: C35.2 U1.32(OA_1-)
N16756983: C34.2 U1.33(OA_1+)
N16757079: C36.2 U1.31(OA_2+)
N16757083: C37.2 U1.30(OA_2-)
N16757087: C38.2 U1.29(OA_3+)
N16757091: C39.2 U1.28(OA_3-)
N16766495: D2.1(CATHODE) U1.27(ALL_DONE)
N16781830: C28.2 U1.40(OB_2+)
N16781832: C29.2 U1.39(OB_2-)
N16781834: C30.2 U1.38(OB_3+)
N16781836: C31.2 U1.37(OB_3-)
N143603151: R8.2 SW1.4(A4)
N143603431: R10.2 SW1.5(A5)
N143603671: R7.2 SW1.3(A3)
N143605131: R3.2 SW1.2(A2)
N143605431: R12.2 SW1.6(A6)
N143605671: R1.2 SW1.1(A1)
N144872111: R23.2 SW4.6(A6)
N144872810: R13.2 SW4.1(A1)
N144872811: R16.2 SW4.2(A2)
N144872812: R18.2 SW4.3(A3)
N144872813: R19.2 SW4.4(A4)
N144872814: R21.2 SW4.5(A5)
N144873671: R20.2 SW3.4(A4)
N144874091: R24.2 SW3.6(A6)
N144874331: R22.2 SW3.5(A5)
N144874811: R15.2 SW3.3(A3)
N144875811: R14.2 SW3.1(A1)
N144876491: R17.2 SW3.2(A2)
N144883340: R35.2 SW8.1(A1)
N144883341: R36.2 SW8.2(A2)
N144883342: R37.2 SW8.3(A3)
N144883343: R38.2 SW8.4(A4)
N144883344: R39.2 SW8.5(A5)
N144883345: R40.2 SW8.6(A6)
N144883781: R25.2 SW5.1(A1)
N144886021: R27.2 SW5.2(A2)
N144888661: R33.2 SW5.6(A6)
N144889101: R29.2 SW5.3(A3)
N144890181: R31.2 SW5.4(A4)
N144890984: R32.2 SW5.5(A5)
N167546071: R60.2 SW11.6(A6)
N167546690: R50.2 SW11.1(A1)
N167546691: R51.2 SW11.2(A2)
N167546692: R54.2 SW11.3(A3)
N167546693: R56.2 SW11.4(A4)
N167546694: R58.2 SW11.5(A5)
N167547371: R57.2 SW12.4(A4)
N167547671: R61.2 SW12.6(A6)
N167547831: R59.2 SW12.5(A5)
N167548151: R55.2 SW12.3(A3)
N167549111: R52.2 SW12.1(A1)
N167549751: R53.2 SW12.2(A2)
N167550950: R72.2 SW18.1(A1)
N167550951: R73.2 SW18.2(A2)
N167550952: R75.2 SW18.3(A3)
N167550953: R76.2 SW18.4(A4)
N167550954: R77.2 SW18.5(A5)
N167550955: R78.2 SW18.6(A6)
N167551251: R62.2 SW14.1(A1)
N167552231: R66.2 SW14.2(A2)
N167554851: R70.2 SW14.6(A6)
N167555071: R67.2 SW14.3(A3)
N167555691: R68.2 SW14.4(A4)
N167556734: R69.2 SW14.5(A5)
N167558911: R47.2 SW10.4(A4)
N167559111: R48.2 SW10.5(A5)
N167559271: R45.2 SW10.3(A3)
N167559851: R46.2 SW10.2(A2)
N167560011: R49.2 SW10.6(A6)
N167560171: R44.2 SW10.1(A1)
N167582101: R30.2 SW6.3(A3)
N167582261: R26.2 SW6.1(A1)
N167582481: R28.2 SW6.2(A2)
N167598171: R65.2 SW15.3(A3)
N167598391: R63.2 SW15.1(A1)
N167598551: R64.2 SW15.2(A2)
N167665790: D2.2(ANODE) R71.1
N167695010: D1.2(ANODE) R34.1

Pads without a net: J1 2; U1 23; U2 23

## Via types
v1: diameter 0.508, hole 0.254, TOP to BOTTOM, 652 vias
v2: diameter 0.508, hole 0.255, TOP to BOTTOM, 14 vias
v3: diameter 0.406, hole 0.203, TOP to BOTTOM, 74 vias

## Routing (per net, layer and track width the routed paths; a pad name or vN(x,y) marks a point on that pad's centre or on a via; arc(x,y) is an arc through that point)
GND: length 49.1
  TOP w0.381: R65.1 v1(195.06,58.94) ; R64.1 v1(195.06,56.4)
  TOP w0.508: R37.1 214.91,71.75 v1(214.91,71.75) ; R53.1 v1(214.91,51.34) ; R36.1 v1(214.91,69.12) ; R29.1 v1(214.78,18.32) ; v1(179.23,27.04) R43.1 ; R30.1 v1(196.86,16.32) ; v1(151.63,10.33) R11.1 ; R55.1 v1(214.91,53.88) ; R40.1 v1(214.91,79.28) ; R48.1 v1(214.78,41.18) ; R28.1 v1(196.86,13.78) ; R7.1 v1(214.91,89.44) ; R45.1 v1(214.78,36.1) ; R12.1 v1(214.91,97.06) ; R33.1 v1(214.78,25.94) ; R39.1 v1(214.91,76.74) ; R27.1 v1(214.78,15.78) ; R61.1 v1(214.91,61.5) ; R3.1 v1(214.91,86.9) ; SW17.2 v1(191.7,66.31) ; R59.1 v1(214.91,58.96) ; v1(151.63,15.41) R4.1 ; v1(178.19,50.69) R80.1 ; R32.1 v1(214.78,23.4) ; R10.1 v1(214.91,94.52) ; R46.1 v1(214.78,33.56) ; v1(151.63,12.87) R9.1 ; R49.1 v1(214.78,43.72)
  BOTTOM w0.381: R24.1 v1(215.91,65.8) ; R23.1 v1(215.91,83.58) ; R15.1 v1(215.91,73.42) ; R21.1 v1(215.91,86.12) ; R32.1 v1(215.71,22.62) ; R75.1 v1(215.91,55.64) ; R73.1 v1(215.91,58.18) ; R77.1 v1(215.71,50.56) ; R18.1 v1(215.91,91.2) ; R54.1 v1(215.71,20.08) ; R67.1 v1(215.71,37.86) ; R17.1 v1(215.91,75.96) ; R27.1 v1(215.71,15) ; R16.1 v1(215.91,93.74) ; R48.1 v1(215.71,40.4) ; R22.1 v1(215.91,68.34) ; R78.1 v1(215.71,48.02) ; R46.1 v1(215.58,32.78) ; R60.1 v1(215.71,12.46)
  BOTTOM w0.508: R70.1 v1(215.66,30.24) ; SW9.2 v1(198.72,78.75) ; SW9.1 v1(198.72,81.29)
  vias: v1(22.23,73.09) v1(22.23,72.25) v1(22.19,70.97) v1(22.22,70.14) v1(23.09,73.81) v1(23.24,71.59) v1(69.49,60.35) v1(69.49,57.93) v1(70.26,48.06) v1(70.26,45.65) v1(71.56,57.9) v1(71.56,55.48) v1(71.7,50.08) v1(71.7,47.67) v1(80.98,62.47) v1(83.39,62.47) v1(83.41,60.8) v1(84.94,48.96) v1(84.94,46.55) v1(85.82,60.8) v1(86.65,57.52) v1(86.65,55.11) v1(98.07,67.85) v1(98.07,66.21) v1(98.07,65.03) v1(98.07,63.85) v1(98.07,62.21) v1(98.07,61.03) v1(98.07,59.85) v1(98.07,58.21) v1(98.07,57.03) v1(98.07,55.85) v1(98.07,54.21) v1(98.07,53.03) v1(98.07,51.85) v1(98.07,50.21) v1(98.07,49.03) v1(98.07,47.85) v1(98.07,46.21) v1(98.07,45.03) v1(98.07,43.85) v1(98.07,42.21) v1(98.07,41.03) v1(98.07,39.85) v1(98.07,38.21) v1(98.88,67.85) v1(98.88,66.21) v1(98.88,63.85) v1(98.88,62.21) v1(98.88,59.85) v1(98.88,58.21) v1(98.88,55.85) v1(98.88,54.21) v1(98.88,51.85) v1(98.88,50.21) v1(98.88,47.85) v1(98.88,46.21) v1(98.88,43.85) v1(98.88,42.21) v1(98.88,39.85) v1(98.88,38.21) v1(99.69,67.85) v1(99.69,66.21) v1(99.69,63.85) v1(99.69,62.21) v1(99.69,59.85) v1(99.69,58.21) v1(99.69,55.85) v1(99.69,54.21) v1(99.69,51.85) v1(99.69,50.21) v1(99.69,47.85) v1(99.69,46.21) v1(99.69,43.85) v1(99.69,42.21) v1(99.69,39.85) v1(99.69,38.21) v1(100.5,68.13) v1(100.5,65.93) v1(100.5,64.13) v1(100.5,61.93) v1(100.5,60.13) v1(100.5,57.93) v1(100.5,56.13) v1(100.5,53.93) v1(100.5,52.13) v1(100.5,49.93) v1(100.5,48.13) v1(100.5,45.93) v1(100.5,44.13) v1(100.5,41.93) v1(100.5,40.13) v1(100.5,37.93) v1(101.28,67.81) v1(101.28,66.25) v1(101.28,63.81) v1(101.28,62.25) v1(101.28,59.81) v1(101.28,58.25) v1(101.28,55.81) v1(101.28,54.25) v1(101.28,51.81) v1(101.28,50.25) v1(101.28,47.81) v1(101.28,46.25) v1(101.28,43.81) v1(101.28,42.25) v1(101.28,39.81) v1(101.28,38.25) v1(101.6,67.03) v1(101.6,63.03) v1(101.6,59.03) v1(101.6,55.03) v1(101.6,51.03) v1(101.6,47.03) v1(101.6,43.03) v1(101.6,39.03) v1(103.4,67.03) v1(103.4,63.03) v1(103.4,59.03) v1(103.4,55.03) v1(103.4,51.03) v1(103.4,47.03) v1(103.4,43.03) v1(103.4,39.03) v1(103.72,67.81) v1(103.72,66.25) v1(103.72,63.81) v1(103.72,62.25) v1(103.72,59.81) v1(103.72,58.25) v1(103.72,55.81) v1(103.72,54.25) v1(103.72,51.81) v1(103.72,50.25) v1(103.72,47.81) v1(103.72,46.25) v1(103.72,43.81) v1(103.72,42.25) v1(103.72,39.81) v1(103.72,38.25) v1(104.5,68.13) v1(104.5,65.93) v1(104.5,64.13) v1(104.5,61.93) v1(104.5,60.13) v1(104.5,57.93) v1(104.5,56.13) v1(104.5,53.93) v1(104.5,52.13) v1(104.5,49.93) v1(104.5,48.13) v1(104.5,45.93) v1(104.5,44.13) v1(104.5,41.93) v1(104.5,40.13) v1(104.5,37.93) v1(105.31,67.85) v1(105.31,66.21) v1(105.31,63.85) v1(105.31,62.21) v1(105.31,59.85) v1(105.31,58.21) v1(105.31,55.85) v1(105.31,54.21) v1(105.31,51.85) v1(105.31,50.21) v1(105.31,47.85) v1(105.31,46.21) v1(105.31,43.85) v1(105.31,42.21) v1(105.31,39.85) v1(105.31,38.21) v1(106.12,67.85) v1(106.12,66.21) v1(106.12,63.85) v1(106.12,62.21) v1(106.12,59.85) v1(106.12,58.21) v1(106.12,55.85) v1(106.12,54.21) v1(106.12,51.85) v1(106.12,50.21) v1(106.12,47.85) v1(106.12,46.21) v1(106.12,43.85) v1(106.12,42.21) v1(106.12,39.85) v1(106.12,38.21) v1(106.93,67.85) v1(106.93,66.21) v1(106.93,65.03) v1(106.93,63.85) v1(106.93,62.21) v1(106.93,61.03) v1(106.93,59.85) v1(106.93,58.21) v1(106.93,57.03) v1(106.93,55.85) v1(106.93,54.21) v1(106.93,53.03) v1(106.93,51.85) v1(106.93,50.21) v1(106.93,49.03) v1(106.93,47.85) v1(106.93,46.21) v1(106.93,45.03) v1(106.93,43.85) v1(106.93,42.21) v1(106.93,41.03) v1(106.93,39.85) v1(106.93,38.21) v1(124.53,80.02) v1(124.53,76.02) v1(124.81,82.45) v1(124.81,81.64) v1(124.81,80.83) v1(124.81,75.21) v1(124.81,74.4) v1(124.81,73.59) v1(124.85,79.24) v1(124.85,76.8) v1(125.63,78.92) v1(125.63,77.12) v1(126.41,79.24) v1(126.41,76.8) v1(126.45,82.45) v1(126.45,81.64) v1(126.45,80.83) v1(126.45,75.21) v1(126.45,74.4) v1(126.45,73.59) v1(126.73,80.02) v1(126.73,76.02) v1(127.63,82.45) v1(127.63,73.59) v1(128.53,80.02) v1(128.53,76.02) v1(128.81,82.45) v1(128.81,81.64) v1(128.81,80.83) v1(128.81,75.21) v1(128.81,74.4) v1(128.81,73.59) v1(128.85,79.24) v1(128.85,76.8) v1(129.63,78.92) v1(129.63,77.12) v1(130.07,42.11) v1(130.07,39.69) v1(130.41,79.24) v1(130.41,76.8) v1(130.45,82.45) v1(130.45,81.64) v1(130.45,80.83) v1(130.45,75.21) v1(130.45,74.4) v1(130.45,73.59) v1(130.73,80.02) v1(130.73,76.02) v1(131.3,56.74) v1(131.3,54.32) v1(131.63,82.45) v1(131.63,73.59) v1(131.64,44.85) v1(131.64,42.44) v1(132.53,80.02) v1(132.53,76.02) v1(132.81,82.45) v1(132.81,81.64) v1(132.81,80.83) v1(132.81,75.21) v1(132.81,74.4) v1(132.81,73.59) v1(132.85,79.24) v1(132.85,76.8) v1(132.9,59.4) v1(132.9,56.99) v1(133.63,78.92) v1(133.63,77.12) v1(133.98,39.97) v1(134.41,79.24) v1(134.41,76.8) v1(134.45,82.45) v1(134.45,81.64) v1(134.45,80.83) v1(134.45,75.21) v1(134.45,74.4) v1(134.45,73.59) v1(134.73,80.02) v1(134.73,76.02) v1(135.63,82.45) v1(135.63,73.59) v1(136.2,58.45) v1(136.39,39.97) v1(136.53,80.02) v1(136.53,76.02) v1(136.57,37.95) v1(136.81,82.45) v1(136.81,81.64) v1(136.81,80.83) v1(136.81,75.21) v1(136.81,74.4) v1(136.81,73.59) v1(136.85,79.24) v1(136.85,76.8) v1(137.63,78.92) v1(137.63,77.12) v1(138.41,79.24) v1(138.41,76.8) v1(138.45,82.45) v1(138.45,81.64) v1(138.45,80.83) v1(138.45,75.21) v1(138.45,74.4) v1(138.45,73.59) v1(138.61,58.45) v1(138.57,56.76) v1(138.73,80.02) v1(138.73,76.02) v1(138.84,39.97) v1(138.98,37.95) v1(139.63,82.45) v1(139.63,73.59) v1(140.53,80.02) v1(140.53,76.02) v1(140.81,82.45) v1(140.81,81.64) v1(140.81,80.83) v1(140.81,75.21) v1(140.81,74.4) v1(140.81,73.59) v1(140.85,79.24) v1(140.85,76.8) v1(140.98,56.76) v1(141.24,37.95) v1(141.26,39.97) v1(141.63,78.92) v1(141.63,77.12) v1(142.41,79.24) v1(142.41,76.8) v1(142.45,82.45) v1(142.45,81.64) v1(142.45,80.83) v1(142.45,75.21) v1(142.45,74.4) v1(142.45,73.59) v1(142.73,80.02) v1(142.73,76.02) v1(143.63,82.45) v1(143.63,73.59) v1(143.64,39.97) v1(143.65,37.95) v1(144.53,80.02) v1(144.53,76.02) v1(144.81,82.45) v1(144.81,81.64) v1(144.81,80.83) v1(144.81,75.21) v1(144.81,74.4) v1(144.81,73.59) v1(144.85,79.24) v1(144.85,76.8) v1(145.63,78.92) v1(145.63,77.12) v1(146.06,39.97) v1(146.41,79.24) v1(146.41,76.8) v1(146.45,82.45) v1(146.45,81.64) v1(146.45,80.83) v1(146.45,75.21) v1(146.45,74.4) v1(146.45,73.59) v1(146.73,80.02) v1(146.73,76.02) v1(146.99,37.95) v1(147.63,82.45) v1(147.63,73.59) v1(148.53,80.02) v1(148.53,76.02) v1(148.81,82.45) v1(148.81,81.64) v1(148.81,80.83) v1(148.81,75.21) v1(148.81,74.4) v1(148.81,73.59) v1(148.85,79.24) v1(148.85,76.8) v1(149.4,37.95) v1(149.63,78.92) v1(149.63,77.12) v1(150.41,79.24) v1(150.41,76.8) v1(150.45,82.45) v1(150.45,81.64) v1(150.45,80.83) v1(150.45,75.21) v1(150.45,74.4) v1(150.45,73.59) v1(150.73,80.02) v1(150.73,76.02) v1(151.63,82.45) v1(151.63,73.59) v1(152.53,80.02) v1(152.53,76.02) v1(152.81,82.45) v1(152.81,81.64) v1(152.81,80.83) v1(152.81,75.21) v1(152.81,74.4) v1(152.81,73.59) v1(152.85,79.24) v1(152.85,76.8) v1(153.63,78.92) v1(153.63,77.12) v1(154.41,79.24) v1(154.41,76.8) v1(154.45,82.45) v1(154.45,81.64) v1(154.45,80.83) v1(154.45,75.21) v1(154.45,74.4) v1(154.45,73.59) v1(154.73,80.02) v1(154.73,76.02) v1(173.88,94.75) v1(175.02,94.75) v1(176.29,94.75) v1(177.39,94.83) v3(48.7,54.25) v3(48.9,47.46) v3(48.9,45.06) v3(51.5,53.8) v3(51.46,44.3) v3(51.65,47.05) v3(52.7,56.65) v3(52.7,54.25) v3(52.9,47.46) v3(53.28,45.31) v3(55.21,56.11) v3(55.57,44.39) v3(56.9,47.46) v3(57.13,57.06) v3(57.13,54.66) v3(57.19,45.23) v3(59.14,57.79) v3(59.51,44.35) v3(60.9,47.46) v3(61.18,57.1) v3(61.18,54.7) v3(61.24,45.22) v3(63.63,46.99) v3(63.66,56.62) v3(63.67,54.31) v3(63.73,44.68) v3(76.47,55.24) v3(76.45,52.74) v3(77.12,54.34) v3(77.12,53.17) v3(77.12,52) v3(77.12,50.83) v3(77.12,49.66) v3(77.43,56.46) v3(78.12,55.5) v3(78.12,54.34) v3(78.12,53.17) v3(78.12,52) v3(78.12,50.83) v3(78.12,49.66) v3(78.62,56.96) v3(79.12,54.34) v3(79.12,53.17) v3(79.12,52) v3(79.12,50.83) v3(79.12,49.66) v3(79.54,56.53) v3(79.8,53.27) v3(79.8,50.75) v3(134.88,48.09) v3(135.28,49.21) v3(135.28,48.55) v3(135.27,47.28) v3(135.27,46.56) v3(136.44,49.55) v3(136.44,48.55) v3(136.44,47.55) v3(136.5,50.23) v3(137.61,49.55) v3(137.61,48.55) v3(137.61,47.55) v3(138.52,46.87) v3(138.78,49.55) v3(138.78,48.55) v3(138.78,47.55) v3(139.02,50.24) v3(139.95,49.55) v3(139.95,48.55) v3(139.95,47.55) v3(141,46.84) v3(141.12,49.55) v3(141.12,48.55) v3(141.12,47.55) v3(142.28,48.55)
VDD: length 8.3
  TOP w0.203: v1(132.98,47.89) 132.98,47.93 133.11,48.05 U1.51
  TOP w0.254: U1.36 v1(139.03,52.03) ; U1.41 v1(136.53,52.03) ; U1.9 v1(138.53,45.07) ; U1.14 v1(141.03,45.07)
  BOTTOM w0.203: v1(78.63,58.63) 78.63,58.63 78.62,58.63 U2.51
  BOTTOM w0.254: U2.14 v1(81.6,50.77) ; U2.41 v1(74.64,55.27) ; U2.36 v1(74.64,52.77) ; U2.9 v1(81.6,53.27)
  vias: v1(76.39,59.27) v1(77.36,59.27) v1(79.49,59.22) v1(132.35,47.87) v1(132.42,49.01) v1(132.58,46.39)
VDD_SEL: length 159.2
  TOP w0.254: 144.33,49.55 U1.25
  TOP w0.381: 145.31,49.53 145.29,49.55 144.33,49.55
  TOP w0.889: v1(76.85,47.29) 76.85,43.59 88.52,31.92 147,31.92 151.16,36.08 151.16,43.69 145.31,49.53 145.8,50.02 149.58,50.02 180.85,81.29 v1(186.22,81.29)
  BOTTOM w0.203: U2.25 77.12,48.12 77.12,47.57 76.85,47.3 v1(76.85,47.29)
  BOTTOM w0.635: SW9.4 v1(186.22,81.29)
VIN: length 2
  TOP w0.203: U1.24 144.28,49.05 144.61,48.72 v1(144.61,48.7)
  BOTTOM w0.203: U2.24 77.62,47.67 v1(77.93,47.36)
  vias: v1(173.88,90.06) v1(173.88,88.79) v1(174.89,90.06) v1(174.89,88.79) v1(176.03,90.06) v1(176.03,88.79) v1(177.3,90.06) v1(177.3,88.79) v1(217.87,94.28) v1(217.87,92.37) v1(217.87,90.47) v1(217.87,88.56) v1(217.87,86.66) v1(219.14,94.28) v1(219.14,92.37) v1(219.14,90.47) v1(219.14,88.56) v1(219.14,86.66) v1(220.41,94.28) v1(220.41,92.37) v1(220.41,90.47) v1(220.41,88.56) v1(220.41,86.66)
BOT_EGR_LN1_HOST_N: length 9.5
  TOP w0.178: U3.6 133.63,82.95 arc(133.91,83.62) 134.58,83.89 arc(135.13,84.12) 135.35,84.67 135.35,86.86 135.35,88.47 135.32,88.51 C6.1
BOT_EGR_LN1_HOST_P: length 9.5
  TOP w0.178: C5.1 135.95,88.51 135.91,88.47 135.91,87.09 135.91,84.67 arc(136.14,84.12) 136.69,83.89 arc(137.36,83.62) 137.63,82.95 U3.5
BOT_EGR_LN1_N: length 29.3
  BOTTOM w0.178: U5.L37 54.46,57 arc(54.29,57.03) 54.14,57.13 53.54,57.73 arc(53.43,57.9) 53.39,58.09 53.39,58.97 arc(53.78,59.92) 54.73,60.32 54.94,60.32 arc(55.14,60.28) 55.3,60.17 55.32,60.16 55.49,59.98 arc(55.59,59.91) 55.71,59.89 arc(55.84,59.91) 55.94,59.98 56.19,60.23 arc(56.28,60.29) 56.4,60.32 56.49,60.32 arc(56.68,60.28) 56.85,60.17 57.05,59.96 arc(57.15,59.9) 57.26,59.87 arc(57.37,59.9) 57.46,59.96 57.73,60.23 arc(57.83,60.29) 57.94,60.32 60.96,60.32 arc(61.07,60.29) 61.16,60.23 61.25,60.15 61.45,59.95 arc(61.62,59.87) 61.8,59.95 62.02,60.17 arc(62.18,60.28) 62.38,60.32 62.47,60.32 arc(62.58,60.29) 62.67,60.23 62.95,59.95 arc(63.13,59.88) 63.31,59.95 63.51,60.15 arc(63.69,60.27) 63.91,60.32 64.3,60.32 arc(65,60.18) 65.6,59.78 70.06,55.32 70.33,55.05 arc(71.23,54.45) 72.29,54.24 75.44,54.24 U2.39
BOT_EGR_LN1_P: length 29.3
  BOTTOM w0.178: U5.L36 53.74,56.45 arc(53.8,56.59) 53.74,56.74 53.15,57.34 arc(52.91,57.68) 52.83,58.09 52.83,58.97 arc(53.39,60.32) 54.73,60.88 64.3,60.88 arc(65.22,60.69) 66,60.17 70.45,55.72 70.72,55.44 arc(71.44,54.96) 72.29,54.8 75.44,54.8 75.47,54.77 U2.40
BOT_EGR_LN2_HOST_N: length 9.5
  TOP w0.178: C4.1 143.35,88.47 143.35,84.67 arc(143.13,84.12) 142.58,83.89 arc(141.91,83.62) 141.63,82.95 U3.4
BOT_EGR_LN2_HOST_P: length 9.5
  TOP w0.178: C3.1 143.91,88.47 143.91,84.67 arc(144.14,84.12) 144.69,83.89 arc(145.36,83.62) 145.63,82.95 U3.3
BOT_EGR_LN2_N: length 31.4
  SIG-3 w0.203: v2(71.56,56.25) arc(71.47,56.31) 71.35,56.33 70,56.33 arc(69.36,56.46) 68.83,56.82 68.54,57.11 arc(68.41,57.19) 68.26,57.22 68.03,57.22 arc(67.88,57.25) 67.76,57.33 arc(67.68,57.46) 67.65,57.6 67.65,57.86 arc(67.62,57.99) 67.55,58.09 67.42,58.22 arc(67.32,58.29) 67.2,58.31 67.03,58.31 arc(66.85,58.35) 66.7,58.45 66.68,58.47 arc(66.59,58.6) 66.56,58.76 66.56,58.94 arc(66.53,59.08) 66.45,59.19 66.12,59.52 arc(65.41,60) 64.57,60.16 56.83,60.16 arc(56.7,60.14) 56.59,60.06 56.3,59.77 arc(56.06,59.68) 55.83,59.77 55.6,60.01 arc(55.42,60.12) 55.21,60.16 55.13,60.16 arc(55,60.14) 54.89,60.06 54.54,59.71 arc(54.37,59.64) 54.2,59.71 53.94,59.96 53.9,60.01 arc(53.73,60.12) 53.52,60.16 53.3,60.16 arc(52.82,60.07) 52.41,59.8 arc(52.28,59.6) 52.24,59.38 52.24,59.19 arc(52.14,58.96) 51.91,58.87 51.63,58.87 arc(51.49,58.84) 51.38,58.76 arc(50.99,58.5) 50.52,58.41 50.33,58.41 arc(50.17,58.38) 50.04,58.29 49.83,58.09 arc(49.75,57.97) 49.72,57.83 49.72,57.74 arc(49.73,57.69) 49.76,57.64 arc(49.79,57.6) 49.83,57.57 50.2,57.2 50.2,57.19 50.22,57.18 arc(50.36,57.07) 50.51,57.01 arc(50.7,56.99) U5.L2
  BOTTOM w0.178: v2(71.56,56.25) 71.62,56.3 arc(71.74,56.38) 71.88,56.41 72.58,56.41 arc(72.81,56.37) 73,56.24 73.13,56.11 arc(73.54,55.83) 74.02,55.74 75.44,55.74 75.47,55.76 U2.42
BOT_EGR_LN2_P: length 31.4
  SIG-3 w0.203: U5.L3 49.6,56.3 arc(49.67,56.41) 49.7,56.55 49.7,56.61 arc(49.68,56.69) 49.64,56.75 49.33,57.06 arc(49.28,57.11) 49.24,57.16 arc(49.06,57.43) 49.01,57.76 49.01,57.85 arc(49.1,58.25) 49.33,58.59 49.53,58.79 arc(49.9,59.04) 50.33,59.12 50.52,59.12 arc(50.71,59.16) 50.87,59.27 51.47,59.86 51.91,60.3 arc(52.54,60.73) 53.3,60.88 64.57,60.88 arc(65.68,60.65) 66.63,60.02 69.33,57.32 arc(69.64,57.12) 70,57.05 71.35,57.05 arc(71.47,57.07) v2(71.56,57.13)
  BOTTOM w0.178: U2.43 75.47,56.27 75.44,56.3 74.02,56.3 arc(73.75,56.35) 73.52,56.5 73.39,56.63 arc(73.02,56.88) 72.58,56.97 71.88,56.97 arc(71.74,57) 71.62,57.08 v2(71.56,57.13)
BOT_EGR_LN3_HOST_N: length 9.5
  TOP w0.178: C15.1 127.95,88.51 127.91,88.47 127.91,87.09 127.91,84.67 arc(128.14,84.12) 128.69,83.89 arc(129.36,83.62) 129.63,82.95 U3.7
BOT_EGR_LN3_HOST_P: length 9.5
  TOP w0.178: C16.1 127.32,88.51 127.35,88.47 127.35,86.86 127.35,84.67 arc(127.13,84.12) 126.58,83.89 arc(125.91,83.62) 125.63,82.95 U3.8
BOT_EGR_LN3_N: length 36.2
  SIG-3 w0.203: U5.L34 54.79,54.5 arc(54.72,54.39) 54.69,54.25 54.69,54.19 arc(54.71,54.11) 54.75,54.05 54.92,53.88 arc(55.05,53.79) 55.19,53.76 arc(55.59,53.93) 55.75,54.32 55.75,56.43 arc(55.95,57.45) 56.53,58.32 56.67,58.46 arc(57.63,59.1) 58.75,59.32 62.95,59.32 arc(64.34,59.04) 65.52,58.25 68.1,55.67 arc(68.46,55.14) 68.59,54.5 68.59,54.4 arc(68.65,54.08) 68.83,53.82 69.05,53.6 arc(69.12,53.5) 69.14,53.38 arc(69.12,53.27) 69.05,53.17 68.77,52.89 arc(68.64,52.69) 68.59,52.46 arc(68.64,52.22) 68.77,52.02 69.05,51.74 arc(69.16,51.48) 69.05,51.22 68.83,51 arc(68.65,50.73) 68.59,50.42 68.59,47.98 arc(68.81,47.44) 69.35,47.21 70.04,47.21 arc(70.16,47.24) v2(70.26,47.3)
  BOTTOM w0.178: U2.29 75.47,49.27 75.44,49.3 75.12,49.3 arc(74.53,49.18) 74.04,48.85 73.82,48.63 72.87,47.68 arc(72.27,47.28) 71.57,47.14 70.58,47.14 arc(70.44,47.16) 70.32,47.24 v2(70.26,47.3)
BOT_EGR_LN3_P: length 36.2
  SIG-3 w0.203: U5.L33 53.74,53.8 arc(53.87,53.79) 53.99,53.75 arc(54.09,53.69) 54.17,53.62 54.19,53.61 54.19,53.6 54.42,53.37 arc(54.78,53.14) 55.19,53.05 arc(56.09,53.42) 56.46,54.32 56.46,56.43 arc(56.61,57.18) 57.03,57.81 57.17,57.96 arc(57.9,58.44) 58.75,58.61 62.95,58.61 arc(64.07,58.39) 65.02,57.75 66.26,56.51 67.6,55.17 arc(67.81,54.87) 67.88,54.5 67.88,47.98 arc(68.31,46.93) 69.35,46.5 70.04,46.5 arc(70.16,46.48) v2(70.26,46.41)
  BOTTOM w0.178: v2(70.26,46.41) 70.36,46.52 arc(70.43,46.56) 70.51,46.58 71.56,46.58 arc(71.57,46.58) 71.58,46.58 arc(72.49,46.76) 73.26,47.28 73.6,47.62 74.08,48.1 74.43,48.45 arc(74.75,48.66) 75.12,48.74 75.44,48.74 75.47,48.76 U2.28
BOT_EGR_LN4_HOST_N: length 9.5
  TOP w0.178: C2.1 151.35,88.47 151.35,84.67 arc(151.13,84.12) 150.58,83.89 arc(149.91,83.62) 149.63,82.95 U3.2
BOT_EGR_LN4_HOST_P: length 9.5
  TOP w0.178: C1.1 151.91,88.47 151.91,84.67 arc(152.14,84.12) 152.69,83.89 arc(153.36,83.62) 153.63,82.95 U3.1
BOT_EGR_LN4_N: length 34.7
  SIG-2 w0.203: U5.L5 50.65,54.6 arc(50.5,54.62) 50.37,54.67 arc(50.29,54.72) 50.22,54.78 50.2,54.79 50.2,54.8 49.9,55.1 arc(49.56,55.33) 49.15,55.41 arc(48.8,55.55) 48.66,55.9 48.66,56.34 arc(48.77,56.87) 49.07,57.32 49.74,58 arc(49.81,58.06) 49.87,58.11 arc(50.24,58.34) 50.67,58.46 arc(51.43,58.77) 51.75,59.54 arc(51.93,59.99) 52.39,60.18 52.61,60.18 arc(52.74,60.16) 52.86,60.08 53.34,59.6 arc(53.58,59.5) 53.83,59.6 54.15,59.92 arc(54.44,60.11) 54.78,60.18 arc(54.92,60.16) 55.03,60.08 55.54,59.58 arc(55.78,59.48) 56.02,59.58 56.41,59.97 arc(56.65,60.13) 56.93,60.18 62.09,60.18 arc(62.28,60.15) 62.44,60.04 arc(62.6,59.93) 62.79,59.89 62.98,59.89 arc(63.16,59.93) 63.31,60.03 63.32,60.04 arc(63.48,60.15) 63.67,60.18 63.98,60.18 arc(64.17,60.15) 64.32,60.04 arc(64.48,59.93) 64.67,59.89 64.98,59.89 arc(65.17,59.93) 65.33,60.04 arc(65.49,60.15) 65.68,60.18 66.27,60.18 arc(66.59,60.12) 66.86,59.94 67.47,59.33 arc(68.07,58.92) 68.79,58.78 69.28,58.78 arc(69.39,58.76) v2(69.49,58.69)
  BOTTOM w0.178: U2.44 75.44,56.74 74.82,56.74 arc(74.06,56.89) 73.42,57.32 72.84,57.89 72.43,58.31 arc(71.82,58.72) 71.1,58.86 69.89,58.86 arc(69.67,58.82) v2(69.49,58.69)
BOT_EGR_LN4_P: length 34.7
  SIG-2 w0.203: U5.L6 49.5,54.35 arc(49.47,54.48) 49.4,54.6 arc(49.28,54.67) 49.15,54.7 arc(48.3,55.05) 47.95,55.9 47.95,56.34 arc(48.11,57.15) 48.56,57.83 49.24,58.5 arc(49.33,58.59) 49.42,58.67 arc(49.96,58.99) 50.57,59.16 arc(50.6,59.17) 50.63,59.17 arc(50.65,59.17) 50.67,59.17 arc(50.93,59.28) 51.03,59.54 arc(51.43,60.5) 52.39,60.89 66.27,60.89 arc(66.86,60.78) 67.36,60.44 67.97,59.83 arc(68.35,59.58) 68.79,59.49 69.28,59.49 arc(69.39,59.52) v2(69.49,59.58)
  BOTTOM w0.178: U2.45 75.47,57.27 75.44,57.3 74.82,57.3 arc(74.28,57.4) 73.81,57.71 72.82,58.7 arc(72.03,59.23) 71.1,59.42 69.89,59.42 arc(69.67,59.46) v2(69.49,59.58)
BOT_ING_LN1_HOST_N: length 9.5
  TOP w0.178: U3.16 153.63,73.08 arc(153.36,72.41) 152.69,72.14 arc(152.14,71.91) 151.91,71.36 151.91,67.56 C39.1
BOT_ING_LN1_HOST_P: length 9.5
  TOP w0.178: C38.1 151.35,67.56 151.35,71.36 arc(151.13,71.91) 150.58,72.14 arc(149.91,72.41) 149.63,73.08 U3.15
BOT_ING_LN1_N: length 125.8
  TOP w0.178: v1(148.64,37.95) 148.55,38.04 arc(148.49,38.12) 148.48,38.21 148.48,38.6 arc(148.27,39.65) 147.67,40.54 146.94,41.27 144.43,43.78 143.28,44.93 arc(143.12,45.18) 143.06,45.47 143.06,45.87 U1.18
  BOTTOM w0.178: U5.L18 49.93,44.2 arc(50.11,44.17) 50.25,44.07 51.19,43.13 arc(53.82,41.38) 56.92,40.76 81.01,40.76 arc(82.1,40.54) 83.02,39.92 84.33,38.62 arc(84.95,37.69) 85.17,36.59 85.17,35.32 arc(85.67,32.79) 87.11,30.65 89.07,28.68 89.51,28.24 arc(93.11,25.84) 97.36,24.99 135.68,24.99 arc(139.28,25.71) 142.33,27.75 144.45,29.86 144.46,29.88 146.43,31.84 arc(147.94,34.11) 148.48,36.79 148.48,37.55 arc(148.52,37.76) v1(148.64,37.95)
BOT_ING_LN1_P: length 125.8
  TOP w0.178: v1(147.75,37.95) 147.85,38.04 arc(147.9,38.12) 147.92,38.21 147.92,38.6 arc(147.75,39.44) 147.28,40.14 146.55,40.87 144.03,43.39 142.89,44.54 arc(142.6,44.96) 142.5,45.47 142.5,45.87 U1.17
  BOTTOM w0.178: U5.L17 50.65,44.75 arc(50.59,44.61) 50.65,44.46 51.58,43.53 arc(54.03,41.89) 56.92,41.32 81.01,41.32 arc(82.31,41.06) 83.42,40.32 83.6,40.14 arc(83.73,40.05) 83.88,40.02 84.1,40.02 arc(84.24,39.99) 84.37,39.91 84.44,39.84 arc(84.52,39.71) 84.56,39.56 84.56,39.36 arc(84.59,39.2) 84.68,39.06 84.73,39.01 arc(85.47,37.9) 85.73,36.59 85.73,35.32 arc(86.19,33.01) 87.5,31.04 88.75,29.79 89.9,28.64 arc(93.32,26.35) 97.36,25.55 97.59,25.55 arc(97.81,25.59) 97.99,25.72 98,25.72 arc(98.32,25.85) 98.64,25.72 98.66,25.7 arc(99.02,25.55) 99.38,25.7 99.39,25.7 arc(99.75,25.85) 100.11,25.7 100.11,25.7 arc(100.28,25.59) 100.48,25.55 132.12,25.55 arc(132.37,25.6) 132.58,25.74 132.63,25.79 arc(132.97,25.93) 133.31,25.79 133.39,25.71 arc(133.77,25.55) 134.15,25.71 134.27,25.82 arc(134.39,25.9) 134.54,25.93 134.55,25.93 arc(134.72,25.9) 134.85,25.81 134.92,25.74 arc(135.13,25.6) 135.38,25.55 135.68,25.55 arc(139.07,26.22) 141.94,28.14 143.83,30.03 arc(143.9,30.15) 143.93,30.28 143.93,30.47 arc(143.95,30.58) 144.02,30.67 144.14,30.8 arc(144.24,30.87) 144.35,30.89 144.53,30.89 arc(144.67,30.92) 144.79,31 144.88,31.09 arc(144.96,31.2) 144.98,31.32 144.98,31.49 arc(145.01,31.63) 145.08,31.74 145.17,31.83 arc(145.29,31.91) 145.43,31.94 145.56,31.94 arc(145.72,31.97) 145.86,32.06 146.03,32.24 arc(147.43,34.33) 147.92,36.79 147.92,37.55 arc(147.87,37.76) v1(147.75,37.95)
BOT_ING_LN2_HOST_N: length 9.5
  TOP w0.127: 145.63,76.01 U3.14
  TOP w0.178: U3.14 145.63,73.08 arc(145.36,72.41) 144.69,72.14 arc(144.14,71.91) 143.91,71.36 143.91,67.56 C37.1
BOT_ING_LN2_HOST_P: length 9.5
  TOP w0.178: U3.13 141.63,73.08 arc(141.91,72.41) 142.58,72.14 arc(143.13,71.91) 143.35,71.36 143.35,67.56 C36.1
BOT_ING_LN2_N: length 120.4
  TOP w0.178: U1.16 142.06,45.87 142.06,44.7 arc(142.18,44.07) 142.54,43.53 144.74,41.33 arc(145.03,40.9) 145.13,40.4 145.13,40.21 arc(145.14,40.14) 145.19,40.08 v1(145.29,39.97)
  SIG-2 w0.203: U5.L15 49.74,46.6 arc(49.84,46.59) 49.94,46.57 arc(50.06,46.51) 50.17,46.42 50.19,46.41 50.19,46.4 50.39,46.2 arc(50.91,45.83) 51.53,45.64 arc(51.85,45.53) 51.99,45.23 51.99,43.74 arc(52.14,42.98) 52.57,42.33 arc(54.31,41.16) 56.37,40.75 80.47,40.75 arc(81.67,40.52) 82.69,39.84 86,36.52 94,28.52 arc(96.96,26.54) 100.45,25.85 132.01,25.85 arc(136.47,26.74) 140.25,29.26 143.33,32.34 arc(144.72,34.42) 145.2,36.87 145.2,39.75 arc(145.23,39.87) v1(145.29,39.97)
BOT_ING_LN2_P: length 120.4
  TOP w0.178: v1(144.4,39.97) 144.51,40.08 arc(144.55,40.14) 144.57,40.21 144.57,40.4 arc(144.51,40.69) 144.35,40.94 142.15,43.13 arc(141.67,43.85) 141.5,44.7 141.5,45.87 U1.15
  SIG-2 w0.203: U5.L14 50.79,47.3 arc(50.72,47.19) 50.69,47.05 50.69,46.99 arc(50.71,46.91) 50.75,46.85 50.9,46.7 arc(51.21,46.48) 51.57,46.35 arc(52.37,46.02) 52.7,45.23 52.7,43.74 arc(52.79,43.25) 53.08,42.83 arc(54.59,41.82) 56.37,41.47 80.47,41.47 arc(81.94,41.17) 83.19,40.34 86.51,37.02 94.5,29.02 arc(97.23,27.2) 100.45,26.56 100.67,26.56 arc(100.88,26.6) 101.05,26.72 101.22,26.89 101.45,27.12 arc(101.66,27.25) 101.9,27.3 arc(102.14,27.25) 102.35,27.12 102.57,26.89 102.66,26.81 arc(102.93,26.63) 103.25,26.56 103.42,26.56 arc(103.58,26.59) 103.72,26.68 103.92,26.89 104.14,27.1 arc(104.35,27.25) 104.6,27.3 arc(104.85,27.25) 105.06,27.1 105.27,26.89 arc(105.64,26.65) 106.06,26.56 127.07,26.56 arc(127.24,26.6) 127.38,26.69 127.67,26.98 arc(127.88,27.12) 128.12,27.17 128.13,27.17 arc(128.36,27.12) 128.55,26.99 128.72,26.82 128.85,26.69 arc(129,26.6) 129.17,26.56 129.31,26.56 arc(129.65,26.63) 129.93,26.82 129.98,26.87 arc(130.24,27.04) 130.54,27.1 130.67,27.1 arc(130.85,27.07) 131,26.96 131.14,26.82 131.27,26.69 arc(131.42,26.6) 131.59,26.56 132.01,26.56 arc(136.2,27.39) 139.75,29.77 140.15,30.17 arc(140.25,30.32) 140.29,30.5 arc(140.33,30.68) 140.43,30.83 140.63,31.04 arc(140.78,31.14) 140.96,31.18 arc(141.14,31.21) 141.29,31.31 142.83,32.85 arc(144.06,34.69) 144.49,36.87 144.49,39.75 arc(144.47,39.87) v1(144.4,39.97)
